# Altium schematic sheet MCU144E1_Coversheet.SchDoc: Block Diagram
size 431 x 279 mm; Date: Not shown in title block; ApprovedBy: Not shown in title block; CheckedBy: Not shown in title block; Author: Not shown in title block; CompanyName: Not shown in title block; DrawnBy: Gustavo Martinez; Engineer: Not shown in title block; Organization: Not shown in title block; Address1: Not shown in title block; Address2: Not shown in title block; Address3: Not shown in title block; Address4: Not shown in title block; DocumentNumber: 1; Revision: Use project parameter SCH_Rev; SheetNumber: 1; SheetTotal: 8; PageSetup: Record=PageOptions¦CenterHorizontal=True¦CenterVertical=True¦PrintScale=1.00¦XCorrection=1.00¦YCorrection=1.00¦PrintKind=0¦BorderSize=5000000¦LeftOffset=0¦BottomOffset=0¦Orientation=2¦PaperLength=1000¦PaperWidth=1000¦Scale=100¦PaperSource=15¦PrintQuality=600¦MediaType=1¦DitherType=10¦PaperKind=Letter¦PrintScaleMode=1
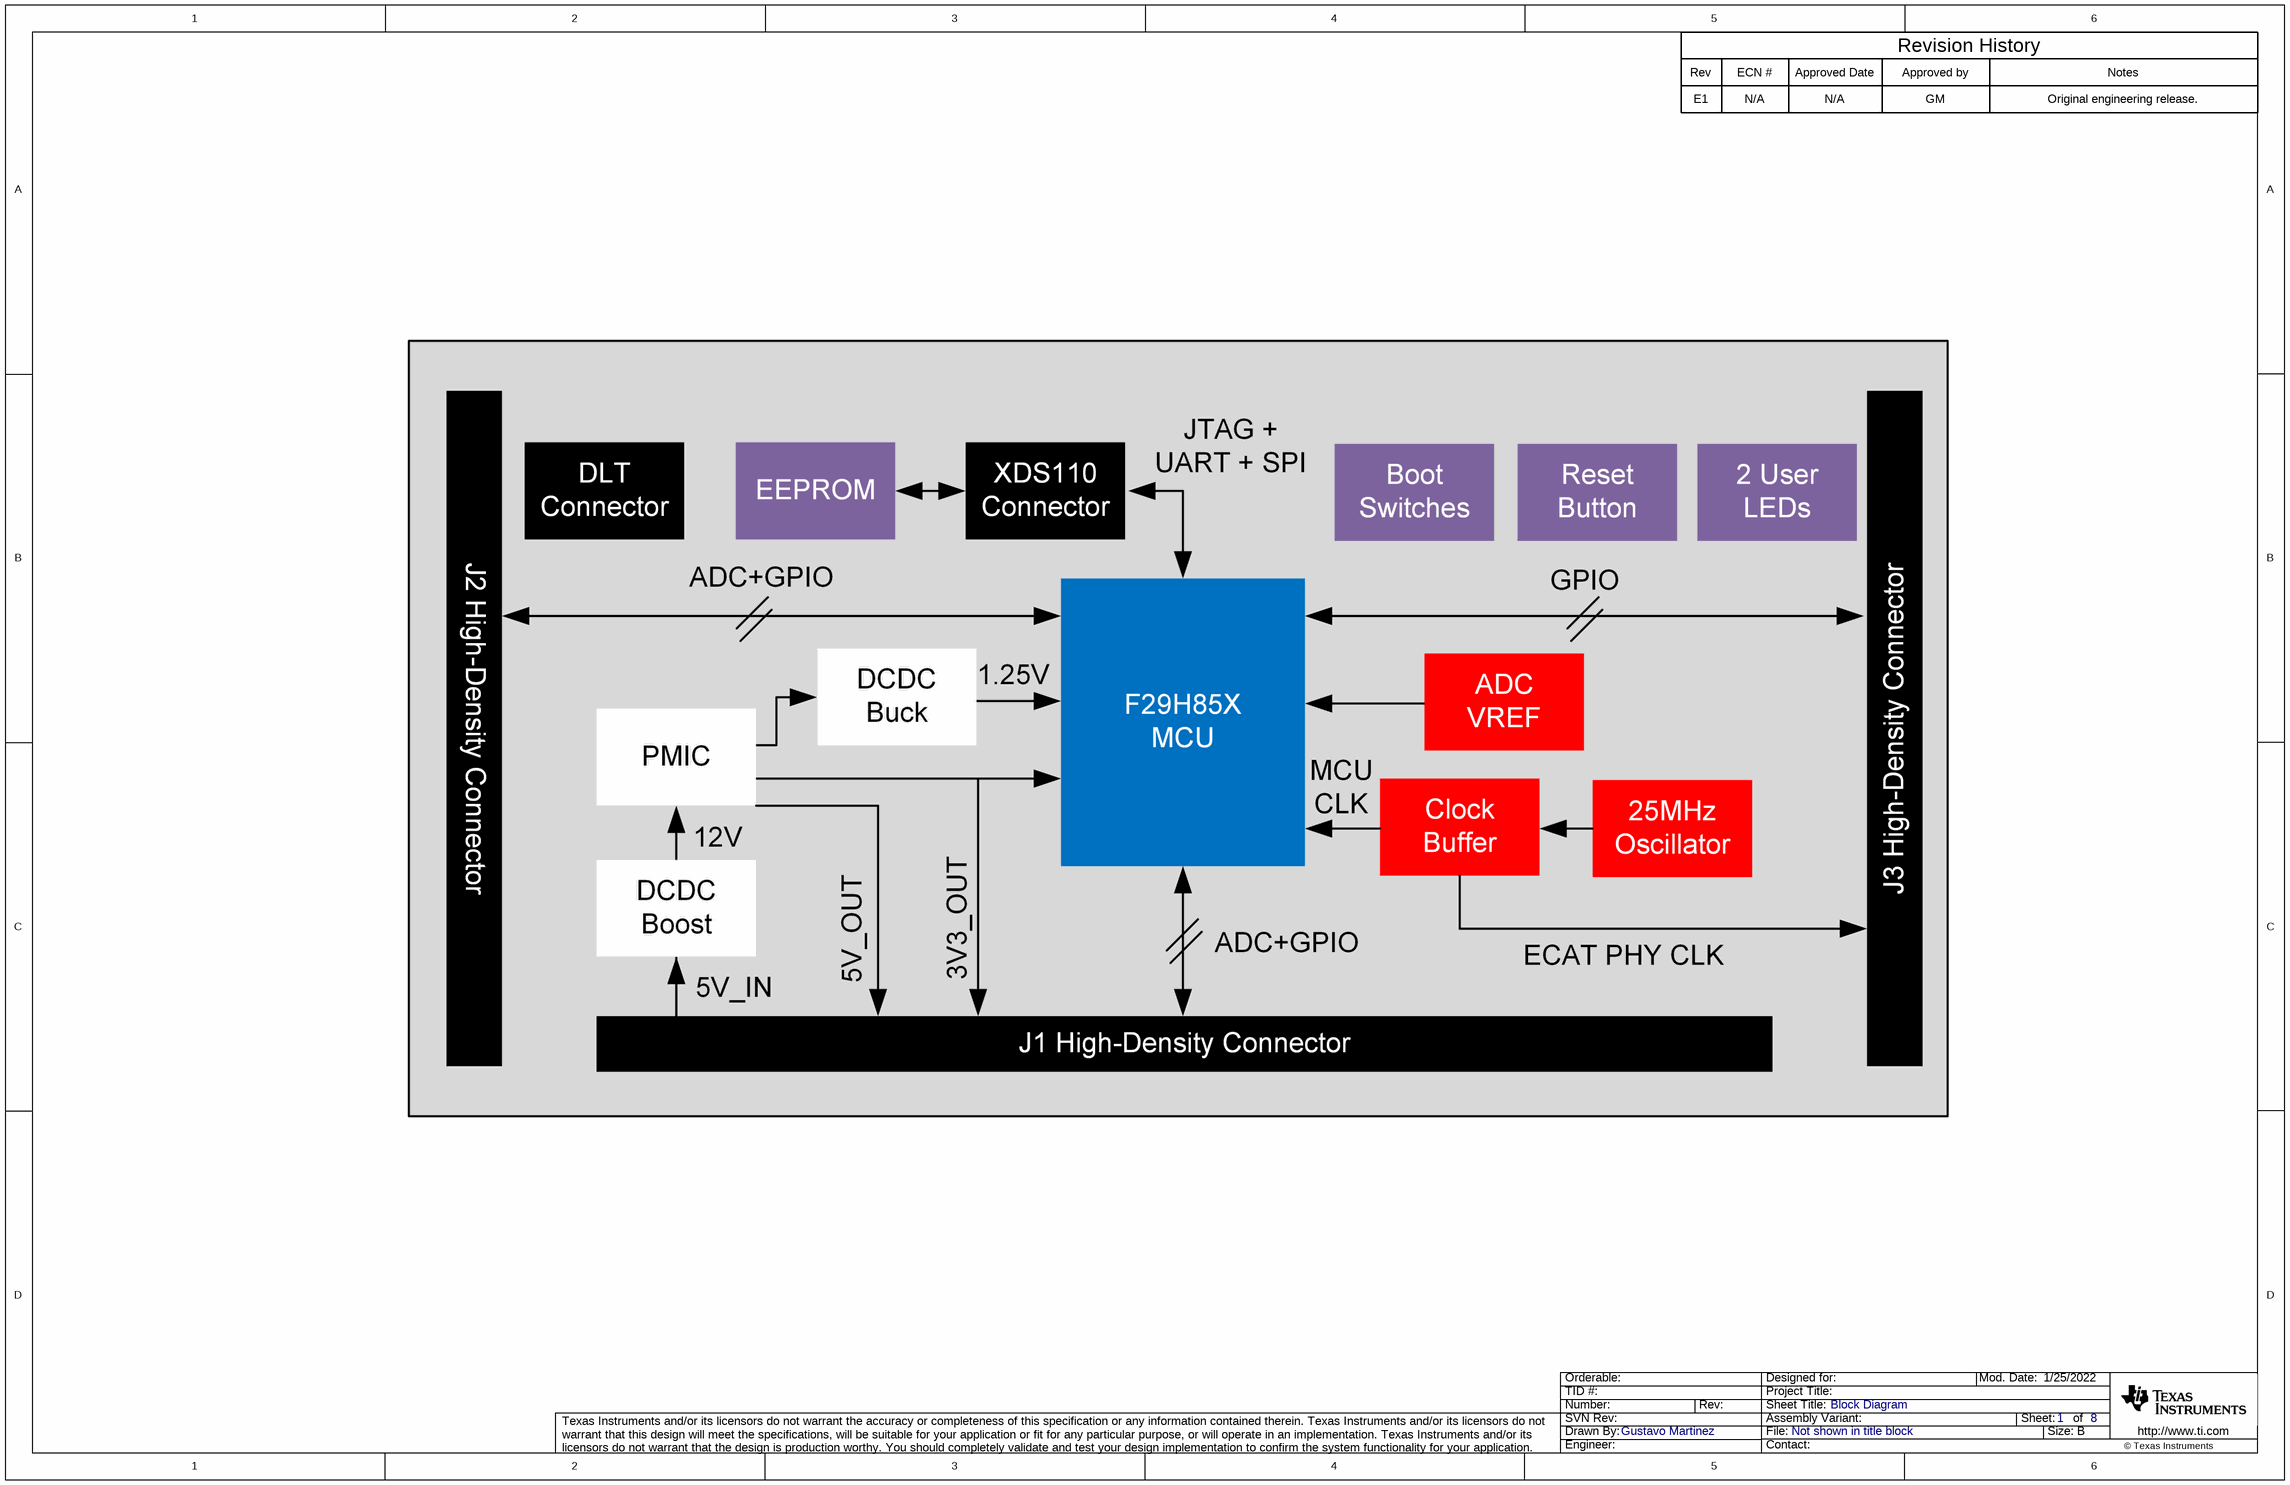
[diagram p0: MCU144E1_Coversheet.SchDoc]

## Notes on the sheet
- Rev
- E1
- ECN #
- N/A
- Approved Date
- Approved by
- GM
- Revision History
- Notes
- Original engineering release.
